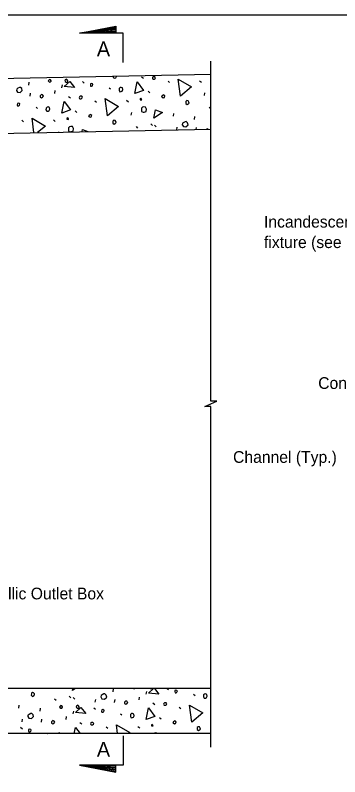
# Model space of a CAD drawing. Extents: x 112544 to 112597.1, y 111084 to 111107.1.
# Drawn here: x 112552.28 to 112556.46, y 111095.54 to 111105.36 of the extents above; entities that cross this region are included whole.
import ezdxf

# ---------------------------------------------------------------- set-up
doc = ezdxf.new("R2010")
doc.units = 0
for name, color, linetype in [('ActivePts-ConstElements', 7, 'Continuous'), ('Dimension', 7, 'Continuous'), ('Miscellaneous', 7, 'Continuous'), ('SupstrConc', 7, 'Continuous'), ('TextStructures', 7, 'Continuous')]:
    doc.layers.add(name, color=color, linetype=linetype)

msp = doc.modelspace()

# ---------------------------------------------------------------- linework, layer by layer
at = {"layer": 'ActivePts-ConstElements'}
msp.add_lwpolyline([(112543.9918, 111085.9039), (112574.7797, 111085.9039), (112574.7797, 111105.3634), (112543.9918, 111105.3634)], close=True, dxfattribs=at)
at = {"layer": 'Dimension'}
for p, q in [((112553.1058, 111105.1304), (112553.5746, 111105.2129)), ((112553.5746, 111105.2029), (112553.1058, 111105.1304)), ((112553.1058, 111105.1304), (112553.5746, 111105.1904)), ((112553.5746, 111105.1766), (112553.1058, 111105.1304)), ((112553.1058, 111105.1304), (112553.5746, 111105.1629)), ((112553.5746, 111105.1479), (112553.1058, 111105.1304)), ((112553.5746, 111095.6721), (112553.1058, 111095.6896)), ((112553.1058, 111095.6896), (112553.5746, 111095.6571)), ((112553.5746, 111095.6434), (112553.1058, 111095.6896)), ((112553.1058, 111095.6896), (112553.5746, 111095.6296)), ((112553.5746, 111095.6171), (112553.1058, 111095.6896)), ((112553.1058, 111095.6896), (112553.5746, 111095.6071))]:
    msp.add_line(p, q, dxfattribs=at)
for points in [[(112553.6683, 111104.7554), (112553.6683, 111105.1304), (112553.1058, 111105.1304), (112553.5746, 111105.2241), (112553.5746, 111105.1304)], [(112554.7971, 111095.9198), (112554.7971, 111100.3149), (112554.7196, 111100.3149), (112554.7971, 111100.3487), (112554.8746, 111100.3824), (112554.7971, 111100.3824), (112554.7971, 111104.7694)], [(112553.6683, 111096.0646), (112553.6683, 111095.6896), (112553.1058, 111095.6896), (112553.5746, 111095.5959), (112553.5746, 111095.6896)]]:
    msp.add_lwpolyline(points, dxfattribs=at)
at = {"layer": 'Miscellaneous'}
for p, q in [((112553.1428, 111104.5065), (112553.1662, 111104.4869)), ((112553.4121, 111104.5735), (112553.4124, 111104.5751)), ((112553.9053, 111104.5685), (112553.931, 111104.5495)), ((112554.2464, 111104.5123), (112554.2667, 111104.4945)), ((112554.6538, 111104.518), (112554.6772, 111104.4984)), ((112552.451, 111104.4609), (112552.4565, 111104.4986)), ((112552.8791, 111104.4281), (112552.8852, 111104.4634)), ((112553.4874, 111104.428), (112553.507, 111104.4126)), ((112552.4704, 111104.3212), (112552.4758, 111104.3588)), ((112552.7876, 111104.3544), (112552.793, 111104.3921)), ((112552.9635, 111104.3161), (112552.9893, 111104.2971)), ((112553.9915, 111104.3819), (112554.0124, 111104.3616)), ((112554.7152, 111104.3274), (112554.7213, 111104.3627)), ((112553.3046, 111104.26), (112553.3249, 111104.2421)), ((112553.712, 111104.2656), (112553.7354, 111104.246)), ((112552.5456, 111104.1757), (112552.5653, 111104.1602)), ((112553.0497, 111104.1296), (112553.0707, 111104.1093)), ((112554.776, 111104.178), (112554.7963, 111104.1602)), ((112553.7735, 111104.075), (112553.7795, 111104.1103)), ((112554.3159, 111104.0599), (112554.3213, 111104.0976)), ((112554.5882, 111104.019), (112554.5937, 111104.0567)), ((112552.3628, 111104.0076), (112552.3832, 111103.9898)), ((112552.7703, 111104.0133), (112552.7936, 111103.9937)), ((112553.8342, 111103.9257), (112553.8545, 111103.9078)), ((112554.024, 111103.961), (112554.045, 111103.9407)), ((112554.0728, 111103.943), (112554.0938, 111103.9228)), ((112554.3588, 111103.8856), (112554.3644, 111103.9176)), ((112554.6092, 111103.8906), (112554.613, 111103.9169)), ((112552.8373, 111103.8552), (112552.8378, 111103.858)), ((112553.266, 111096.6766), (112553.2662, 111096.6779)), ((112553.5384, 111096.6357), (112553.5438, 111096.6734)), ((112554.2342, 111096.6779), (112554.2535, 111096.6617)), ((112552.9742, 111096.5777), (112552.9951, 111096.5574)), ((112553.023, 111096.5597), (112553.044, 111096.5395)), ((112553.8749, 111096.5292), (112553.8804, 111096.5669)), ((112553.9665, 111096.6029), (112553.9726, 111096.6382)), ((112554.5747, 111096.6028), (112554.5944, 111096.5874)), ((112552.3243, 111096.4243), (112552.3297, 111096.4619)), ((112552.7844, 111096.5424), (112552.8047, 111096.5245)), ((112553.3084, 111096.499), (112553.3145, 111096.5343)), ((112553.5577, 111096.4959), (112553.5632, 111096.5336)), ((112554.0508, 111096.4909), (112554.0766, 111096.4719)), ((112552.5966, 111096.3834), (112552.6021, 111096.421)), ((112553.0247, 111096.3505), (112553.0308, 111096.3858)), ((112553.2884, 111096.429), (112553.3118, 111096.4093)), ((112553.633, 111096.3505), (112553.6526, 111096.335)), ((112554.392, 111096.4348), (112554.4123, 111096.4169)), ((112552.3667, 111096.2467), (112552.3727, 111096.282)), ((112552.616, 111096.2436), (112552.6214, 111096.2813)), ((112552.9332, 111096.2768), (112552.9386, 111096.3145)), ((112554.1371, 111096.3044), (112554.158, 111096.2841)), ((112552.3466, 111096.1766), (112552.37, 111096.157)), ((112553.1091, 111096.2386), (112553.1349, 111096.2196)), ((112553.4502, 111096.1824), (112553.4705, 111096.1646)), ((112553.8576, 111096.1881), (112553.881, 111096.1685)), ((112552.6912, 111096.0981), (112552.6956, 111096.0947))]:
    msp.add_line(p, q, dxfattribs=at)
for points in [[(112552.703, 111104.5155), (112552.7172, 111104.5012), (112552.7323, 111104.5026), (112552.74, 111104.5125), (112552.7387, 111104.5173), (112552.73, 111104.5305), (112552.7184, 111104.5352), (112552.7107, 111104.5253), (112552.703, 111104.5155)], [(112552.9086, 111104.4437), (112552.979, 111104.5092), (112553.0416, 111104.4302), (112552.9086, 111104.4437)], [(112552.922, 111104.5095), (112552.9319, 111104.5017), (112552.9452, 111104.5002), (112552.9536, 111104.5076), (112552.9534, 111104.5179), (112552.9478, 111104.5293), (112552.9397, 111104.5401), (112552.9265, 111104.5314), (112552.9181, 111104.524), (112552.922, 111104.5095)], [(112553.5407, 111104.5769), (112553.5404, 111104.5587), (112553.5581, 111104.5505), (112553.5719, 111104.5568), (112553.5832, 111104.5727), (112553.5789, 111104.5785)], [(112553.5414, 111104.5777), (112553.5407, 111104.5769)], [(112554.047, 111104.5417), (112554.0531, 111104.5382), (112554.0689, 111104.5373), (112554.0815, 111104.5484), (112554.0843, 111104.5569), (112554.0756, 111104.5701), (112554.055, 111104.5698), (112554.0467, 111104.5623), (112554.0444, 111104.5514), (112554.047, 111104.5417)], [(112554.4067, 111104.3198), (112554.3787, 111104.54), (112554.5509, 111104.4386), (112554.4067, 111104.3198)], [(112552.2933, 111104.3928), (112552.307, 111104.3706), (112552.3392, 111104.3662), (112552.3685, 111104.3922), (112552.362, 111104.4164), (112552.3448, 111104.4324), (112552.3321, 111104.4316), (112552.3116, 111104.421), (112552.296, 111104.4116), (112552.2933, 111104.3928)], [(112553.2454, 111104.4615), (112553.2493, 111104.4471), (112553.262, 111104.4479), (112553.2735, 111104.4535), (112553.2793, 111104.4706), (112553.2725, 111104.4766), (112553.2609, 111104.4812), (112553.2464, 111104.4773), (112553.2454, 111104.4615)], [(112553.6167, 111104.4187), (112553.6153, 111104.395), (112553.6253, 111104.377), (112553.6428, 111104.3791), (112553.6543, 111104.3847), (112553.6649, 111104.4031), (112553.659, 111104.4248), (112553.6413, 111104.433), (112553.6292, 111104.4298), (112553.6167, 111104.4187)], [(112553.8179, 111104.3535), (112553.8499, 111104.5045), (112553.9312, 111104.3942), (112553.8179, 111104.3535)], [(112552.5989, 111104.3245), (112552.5986, 111104.3063), (112552.6163, 111104.2981), (112552.6301, 111104.3044), (112552.6414, 111104.3204), (112552.6333, 111104.3312), (112552.6266, 111104.3371), (112552.6156, 111104.3394), (112552.6108, 111104.3381), (112552.5989, 111104.3245)], [(112553.1052, 111104.2894), (112553.1113, 111104.2858), (112553.1271, 111104.2849), (112553.1397, 111104.296), (112553.1426, 111104.3046), (112553.1339, 111104.3178), (112553.1132, 111104.3174), (112553.1049, 111104.31), (112553.1026, 111104.299), (112553.1052, 111104.2894)], [(112554.1661, 111104.3097), (112554.1845, 111104.2991), (112554.199, 111104.3029), (112554.2041, 111104.3224), (112554.1851, 111104.3354), (112554.1767, 111104.328), (112554.1677, 111104.323), (112554.1661, 111104.3097), (112554.1648, 111104.3145)], [(112552.3037, 111104.2092), (112552.3075, 111104.1947), (112552.3203, 111104.1955), (112552.3317, 111104.2012), (112552.3375, 111104.2183), (112552.3307, 111104.2242), (112552.3191, 111104.2289), (112552.3046, 111104.225), (112552.3037, 111104.2092)], [(112552.8761, 111104.1012), (112552.9082, 111104.2521), (112552.9895, 111104.1419), (112552.8761, 111104.1012)], [(112553.4649, 111104.0674), (112553.437, 111104.2877), (112553.6091, 111104.1863), (112553.4649, 111104.0674)], [(112553.886, 111104.2734), (112553.9072, 111104.2713), (112553.9046, 111104.281), (112553.8966, 111104.2918), (112553.8858, 111104.2837), (112553.886, 111104.2734)], [(112554.4765, 111104.2427), (112554.4762, 111104.2245), (112554.4928, 111104.2108), (112554.5084, 111104.2202), (112554.5186, 111104.2307), (112554.5153, 111104.2428), (112554.506, 111104.2584), (112554.4896, 111104.2617), (112554.477, 111104.2506), (112554.4765, 111104.2427)], [(112552.6749, 111104.1663), (112552.6735, 111104.1426), (112552.6835, 111104.1246), (112552.701, 111104.1267), (112552.7125, 111104.1324), (112552.7231, 111104.1508), (112552.7173, 111104.1725), (112552.6995, 111104.1807), (112552.6875, 111104.1774), (112552.6749, 111104.1663)], [(112553.9048, 111104.1646), (112553.9061, 111104.1209), (112553.9269, 111104.111), (112553.939, 111104.1142), (112553.9655, 111104.1213), (112553.9698, 111104.1535), (112553.9555, 111104.1782), (112553.9366, 111104.1809), (112553.9173, 111104.1757), (112553.9048, 111104.1646)], [(112554.0634, 111104.0363), (112554.0865, 111104.1434), (112554.1738, 111104.1072), (112554.0634, 111104.0363)], [(112552.5189, 111103.8488), (112552.4952, 111104.0353), (112552.6673, 111103.9339), (112552.5652, 111103.8498)], [(112552.9442, 111104.0211), (112552.9654, 111104.019), (112552.9629, 111104.0287), (112552.9548, 111104.0394), (112552.944, 111104.0314), (112552.9442, 111104.0211)], [(112553.2243, 111104.0573), (112553.2427, 111104.0467), (112553.2572, 111104.0506), (112553.2623, 111104.0701), (112553.2433, 111104.0831), (112553.235, 111104.0757), (112553.2259, 111104.0707), (112553.2243, 111104.0573), (112553.2231, 111104.0621)], [(112552.963, 111103.9122), (112552.9643, 111103.8686), (112552.9851, 111103.8586), (112552.9972, 111103.8619), (112553.0238, 111103.869), (112553.0281, 111103.9012), (112553.0137, 111103.9258), (112552.9949, 111103.9285), (112552.9755, 111103.9233), (112552.963, 111103.9122)], [(112553.5348, 111103.9904), (112553.5345, 111103.9722), (112553.5511, 111103.9585), (112553.5667, 111103.9679), (112553.5768, 111103.9783), (112553.5736, 111103.9904), (112553.5642, 111104.006), (112553.5478, 111104.0094), (112553.5352, 111103.9983), (112553.5348, 111103.9904)], [(112554.4305, 111103.9509), (112554.4442, 111103.9286), (112554.4764, 111103.9243), (112554.5057, 111103.9503), (112554.4992, 111103.9745), (112554.482, 111103.9905), (112554.4693, 111103.9897), (112554.4488, 111103.9791), (112554.4332, 111103.9697), (112554.4305, 111103.9509)], [(112553.1383, 111103.8612), (112553.1447, 111103.891), (112553.2131, 111103.8627)], [(112554.7654, 111103.8938), (112554.7638, 111103.8952), (112554.7528, 111103.8975), (112554.748, 111103.8962), (112554.7455, 111103.8934)], [(112553.0136, 111096.653), (112553.0189, 111096.6779)], [(112553.0524, 111096.6779), (112553.0136, 111096.653)], [(112553.8026, 111096.6779), (112553.8046, 111096.676), (112553.8197, 111096.6774), (112553.8201, 111096.6779)], [(112553.9959, 111096.6185), (112554.0599, 111096.6779)], [(112554.0712, 111096.6779), (112554.129, 111096.605), (112553.9959, 111096.6185)], [(112554.0174, 111096.6779), (112554.0192, 111096.6765), (112554.0326, 111096.6749), (112554.036, 111096.6779)], [(112554.3328, 111096.6363), (112554.3367, 111096.6218), (112554.3494, 111096.6227), (112554.3608, 111096.6283), (112554.3666, 111096.6454), (112554.3598, 111096.6513), (112554.3482, 111096.656), (112554.3338, 111096.6521), (112554.3328, 111096.6363)], [(112552.4849, 111096.6071), (112552.4846, 111096.5889), (112552.5012, 111096.5752), (112552.5168, 111096.5846), (112552.527, 111096.595), (112552.5237, 111096.6071), (112552.5144, 111096.6227), (112552.4979, 111096.6261), (112552.4854, 111096.615), (112552.4849, 111096.6071)], [(112553.3807, 111096.5676), (112553.3944, 111096.5454), (112553.4266, 111096.541), (112553.4559, 111096.567), (112553.4494, 111096.5912), (112553.4322, 111096.6072), (112553.4194, 111096.6064), (112553.399, 111096.5958), (112553.3834, 111096.5864), (112553.3807, 111096.5676)], [(112554.7041, 111096.5935), (112554.7026, 111096.5698), (112554.7126, 111096.5518), (112554.7302, 111096.5539), (112554.7416, 111096.5595), (112554.7522, 111096.5779), (112554.7464, 111096.5996), (112554.7287, 111096.6078), (112554.7166, 111096.6046), (112554.7041, 111096.5935)], [(112552.8486, 111096.4379), (112552.8628, 111096.4236), (112552.8779, 111096.4251), (112552.8856, 111096.4349), (112552.8843, 111096.4397), (112552.8756, 111096.4529), (112552.864, 111096.4576), (112552.8563, 111096.4478), (112552.8486, 111096.4379)], [(112553.0676, 111096.4319), (112553.0774, 111096.4242), (112553.0908, 111096.4226), (112553.0992, 111096.43), (112553.099, 111096.4403), (112553.0933, 111096.4518), (112553.0853, 111096.4625), (112553.0721, 111096.4538), (112553.0637, 111096.4464), (112553.0676, 111096.4319)], [(112553.6862, 111096.4993), (112553.6859, 111096.4811), (112553.7037, 111096.4729), (112553.7175, 111096.4792), (112553.7288, 111096.4952), (112553.7207, 111096.506), (112553.7139, 111096.5119), (112553.703, 111096.5142), (112553.6981, 111096.5129), (112553.6862, 111096.4993)], [(112554.1926, 111096.4642), (112554.1987, 111096.4606), (112554.2145, 111096.4597), (112554.227, 111096.4708), (112554.2299, 111096.4794), (112554.2212, 111096.4926), (112554.2006, 111096.4922), (112554.1922, 111096.4848), (112554.19, 111096.4738), (112554.1926, 111096.4642)], [(112554.5523, 111096.2422), (112554.5243, 111096.4625), (112554.6964, 111096.3611), (112554.5523, 111096.2422)], [(112552.4389, 111096.3152), (112552.4526, 111096.293), (112552.4848, 111096.2887), (112552.5141, 111096.3147), (112552.5076, 111096.3388), (112552.4904, 111096.3549), (112552.4777, 111096.3541), (112552.4572, 111096.3434), (112552.4416, 111096.3341), (112552.4389, 111096.3152)], [(112553.0542, 111096.3662), (112553.1246, 111096.4317), (112553.1872, 111096.3527), (112553.0542, 111096.3662)], [(112553.391, 111096.384), (112553.3949, 111096.3695), (112553.4076, 111096.3703), (112553.4191, 111096.376), (112553.4248, 111096.393), (112553.4181, 111096.399), (112553.4065, 111096.4037), (112553.392, 111096.3998), (112553.391, 111096.384)], [(112553.7623, 111096.3411), (112553.7609, 111096.3174), (112553.7709, 111096.2994), (112553.7884, 111096.3015), (112553.7998, 111096.3072), (112553.8104, 111096.3255), (112553.8046, 111096.3473), (112553.7869, 111096.3555), (112553.7748, 111096.3522), (112553.7623, 111096.3411)], [(112553.9635, 111096.276), (112553.9955, 111096.4269), (112554.0768, 111096.3167), (112553.9635, 111096.276)], [(112552.7445, 111096.247), (112552.7442, 111096.2288), (112552.7619, 111096.2206), (112552.7757, 111096.2269), (112552.787, 111096.2428), (112552.7789, 111096.2536), (112552.7721, 111096.2596), (112552.7612, 111096.2618), (112552.7564, 111096.2605), (112552.7445, 111096.247)], [(112554.3117, 111096.2321), (112554.3301, 111096.2215), (112554.3446, 111096.2254), (112554.3497, 111096.2449), (112554.3307, 111096.2579), (112554.3223, 111096.2505), (112554.3133, 111096.2455), (112554.3117, 111096.2321), (112554.3104, 111096.2369)], [(112553.0368, 111096.0947), (112553.0537, 111096.1746), (112553.1127, 111096.0947)], [(112553.2508, 111096.2118), (112553.2569, 111096.2083), (112553.2727, 111096.2073), (112553.2853, 111096.2185), (112553.2882, 111096.227), (112553.2794, 111096.2402), (112553.2588, 111096.2399), (112553.2505, 111096.2324), (112553.2482, 111096.2215), (112553.2508, 111096.2118)], [(112553.5972, 111096.0947), (112553.5826, 111096.2101), (112553.7547, 111096.1087), (112553.7376, 111096.0947)], [(112554.0315, 111096.1959), (112554.0528, 111096.1938), (112554.0502, 111096.2034), (112554.0422, 111096.2142), (112554.0314, 111096.2062), (112554.0315, 111096.1959)], [(112554.6221, 111096.1652), (112554.6218, 111096.147), (112554.6384, 111096.1333), (112554.654, 111096.1427), (112554.6642, 111096.1531), (112554.6609, 111096.1652), (112554.6516, 111096.1808), (112554.6351, 111096.1842), (112554.6226, 111096.1731), (112554.6221, 111096.1652)], [(112552.4493, 111096.1316), (112552.4531, 111096.1171), (112552.4659, 111096.118), (112552.4773, 111096.1236), (112552.4831, 111096.1407), (112552.4763, 111096.1466), (112552.4647, 111096.1513), (112552.4502, 111096.1474), (112552.4493, 111096.1316)], [(112552.8629, 111096.0947), (112552.8628, 111096.0949), (112552.8451, 111096.1031), (112552.833, 111096.0999), (112552.8271, 111096.0947)], [(112554.1045, 111096.0947), (112554.1011, 111096.1006), (112554.0822, 111096.1033), (112554.0629, 111096.0981), (112554.059, 111096.0947)]]:
    msp.add_lwpolyline(points, dxfattribs=at)
at = {"layer": 'SupstrConc'}
for p, q in [((112544.6086, 111104.3991), (112554.7971, 111104.6028)), ((112551.8027, 111103.8345), (112554.7971, 111103.8944)), ((112554.7971, 111096.6779), (112551.0527, 111096.6779)), ((112554.7971, 111096.0946), (112550.511, 111096.0946))]:
    msp.add_line(p, q, dxfattribs=at)

# ---------------------------------------------------------------- texts
at = {"layer": 'Dimension'}
for s, p in [('Incandescent Light', (112555.4835, 111102.6236)), ('fixture (see Note 15)', (112555.4835, 111102.3596)), ('Channel (Typ.)', (112555.0847, 111099.5882))]:
    msp.add_text(s, height=0.1512, dxfattribs=at).set_placement(p)
at = {"layer": 'TextStructures'}
for s, height, p in [('A', 0.192, (112553.3289, 111104.8327)), ('Conduit (120V)', 0.1512, (112556.1823, 111100.5422)), ('Nonmetallic Outlet Box', 0.1512, (112551.3644, 111097.8267)), ('A', 0.192, (112553.3289, 111095.7953))]:
    msp.add_text(s, height=height, dxfattribs=at).set_placement(p)

doc.saveas('drawing.dxf')
